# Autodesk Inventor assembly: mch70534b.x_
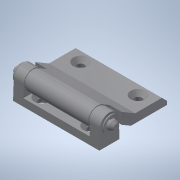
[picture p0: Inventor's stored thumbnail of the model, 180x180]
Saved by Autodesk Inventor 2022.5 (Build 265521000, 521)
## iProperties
Part Number: mch70534b.x_
Material: 一般
Document SubType Name: Assembly
Designer: ImaoCorp
Sending System: SOLIDWORKS 2017-2017317
MC: AMD64
MC_MODEL: Intel64 Family 6 Model 60 Stepping 3, GenuineIntel
OS: Windows_NT
FRU: Parasolid Version 29.0, build 201,  4-17-2017
FORMAT: text
GUISE: transmit
KEY: mch70534b
FILE: mch70534b.x_t
DATE: Fri Jul 26 11:41:35 2019
Author: ImaoCorp
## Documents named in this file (4)
- X:\14_SW2022-Inv2022\00_全2023-1023新製品(TCC)まで\m\mch70534b\MCH70534B.iam
- X:\14_SW2022-Inv2022\00_全2023-1023新製品(TCC)まで\m\mch70534b\mch70534b_01.ipt
- X:\14_SW2022-Inv2022\00_全2023-1023新製品(TCC)まで\m\mch70534b\mch70534b_02.ipt
- X:\14_SW2022-Inv2022\00_全2023-1023新製品(TCC)まで\m\mch70534b\mch70534b_03.ipt
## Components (3 placed, 3 different names)
1. mch70534b_01
2. mch70534b_02
3. mch70534b_03
